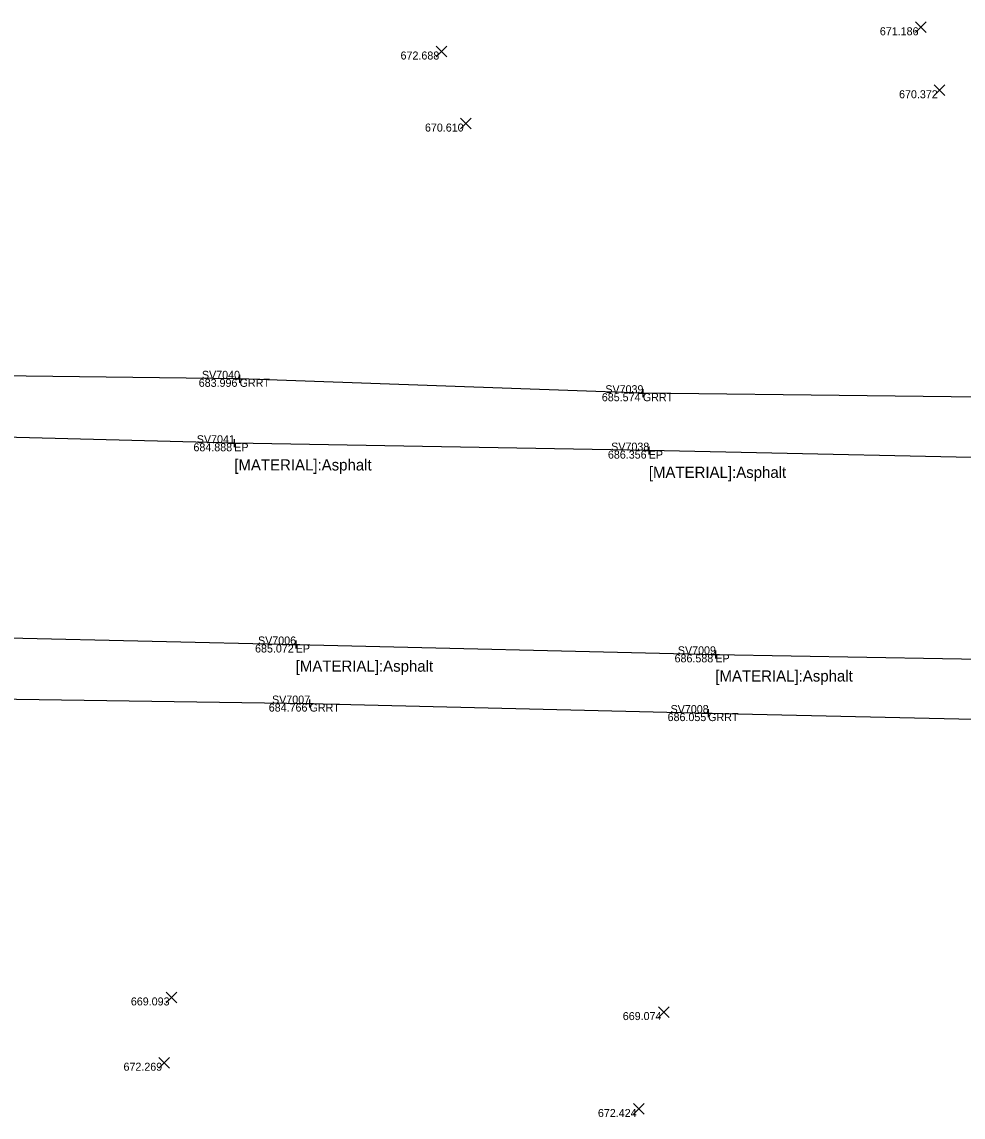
# Model space of a CAD drawing. Extents: x 1660019 to 1662995, y 619975 to 620342.
# Drawn here: x 1660723.1 to 1660840.7, y 620172.3 to 620309.1 of the extents above; entities that cross this region are included whole.
import ezdxf

# ---------------------------------------------------------------- set-up
doc = ezdxf.new("R2010")
doc.units = 0
for name, color, linetype in [('BR_X_Rail_Object', 7, 'Continuous'), ('PV_X_EOP', 7, 'Continuous'), ('RD_P_GR_Lt', 7, 'Continuous'), ('RD_P_GR_Rt', 7, 'Continuous'), ('RD_X_GR_Bar', 7, 'Continuous'), ('RD_X_GR_Rt', 7, 'Continuous'), ('RD_X_Wall', 7, 'Continuous'), ('SV_X_Text', 7, 'Continuous')]:
    doc.layers.add(name, color=color, linetype=linetype)

msp = doc.modelspace()

# ---------------------------------------------------------------- linework, layer by layer
at = {"layer": 'PV_X_EOP'}
for points in [[(1661208.92, 620246.9), (1661156.94, 620248.21), (1661087.29, 620250.6), (1661037.39, 620250.48), (1660981.01, 620252.16), (1660916.41, 620253.34), (1660855.2, 620254.44), (1660801.44, 620255.57), (1660749.64, 620256.49), (1660700.03, 620257.78), (1660643.44, 620258.64), (1660593.17, 620259.57)], [(1660597.37, 620234.1), (1660651.64, 620233.44), (1660703.42, 620232.61), (1660757.32, 620231.35), (1660809.76, 620230.12), (1660857.03, 620229.26), (1660910.07, 620228.44), (1660968.25, 620227.38), (1661028.27, 620226.15), (1661081.58, 620225.11), (1661140.41, 620223.53), (1661201.71, 620222.7)]]:
    msp.add_lwpolyline(points, dxfattribs=at)
at = {"layer": 'RD_P_GR_Lt'}
for p, q in [((1660749.81, 620264.54), (1660750.81, 620264.54)), ((1660750.31, 620265.04), (1660750.31, 620264.04)), ((1660750.31, 620264.54), (1660750.31, 620264.54)), ((1660800.7, 620263.24), (1660800.7, 620262.24)), ((1660800.2, 620262.74), (1660801.2, 620262.74)), ((1660800.7, 620262.74), (1660800.7, 620262.74)), ((1660749.14, 620256.49), (1660750.14, 620256.49)), ((1660749.64, 620256.99), (1660749.64, 620255.99)), ((1660749.64, 620256.49), (1660749.64, 620256.49)), ((1660800.94, 620255.57), (1660801.94, 620255.57)), ((1660801.44, 620256.07), (1660801.44, 620255.07)), ((1660801.44, 620255.57), (1660801.44, 620255.57)), ((1660757.32, 620231.85), (1660757.32, 620230.85)), ((1660756.82, 620231.35), (1660757.82, 620231.35)), ((1660757.32, 620231.35), (1660757.32, 620231.35)), ((1660809.26, 620230.12), (1660810.26, 620230.12)), ((1660809.76, 620230.62), (1660809.76, 620229.62)), ((1660809.76, 620230.12), (1660809.76, 620230.12)), ((1660758.55, 620223.97), (1660759.55, 620223.97)), ((1660759.05, 620224.47), (1660759.05, 620223.47)), ((1660759.05, 620223.97), (1660759.05, 620223.97)), ((1660808.86, 620223.28), (1660808.86, 620222.28)), ((1660808.36, 620222.78), (1660809.36, 620222.78)), ((1660808.86, 620222.78), (1660808.86, 620222.78))]:
    msp.add_line(p, q, dxfattribs=at)
at = {"layer": 'RD_P_GR_Rt'}
for p, q in [((1660834.75, 620307.79), (1660836.08, 620309.13)), ((1660834.75, 620309.13), (1660836.08, 620307.79)), ((1660774.86, 620304.76), (1660776.19, 620306.1)), ((1660774.86, 620306.1), (1660776.19, 620304.76)), ((1660837.11, 620299.92), (1660838.45, 620301.26)), ((1660837.11, 620301.26), (1660838.45, 620299.92)), ((1660777.92, 620295.76), (1660779.25, 620297.1)), ((1660777.92, 620297.1), (1660779.25, 620295.76)), ((1660741.12, 620186.59), (1660742.45, 620187.93)), ((1660741.12, 620187.93), (1660742.45, 620186.59)), ((1660802.64, 620184.76), (1660803.98, 620186.1)), ((1660802.64, 620186.1), (1660803.98, 620184.76)), ((1660740.22, 620178.43), (1660741.55, 620179.77)), ((1660740.22, 620179.77), (1660741.55, 620178.43)), ((1660799.54, 620172.66), (1660800.87, 620173.99)), ((1660799.54, 620173.99), (1660800.87, 620172.66))]:
    msp.add_line(p, q, dxfattribs=at)
at = {"layer": 'RD_X_GR_Rt'}
for points in [[(1661224.69, 620250.79), (1661156.18, 620253.35), (1661087.54, 620257.19), (1661037.26, 620258.5), (1660981.37, 620259.47), (1660918.68, 620260.81), (1660856.77, 620262.08), (1660800.7, 620262.74), (1660750.31, 620264.54), (1660700.27, 620265.16), (1660644.43, 620266.52), (1660592.86, 620267.53)], [(1660596.86, 620226.32), (1660650.68, 620225.81), (1660702.7, 620224.83), (1660759.05, 620223.97), (1660808.86, 620222.78), (1660856.77, 620221.69), (1660908.98, 620220.55), (1660971.26, 620219.59), (1661027.54, 620217.92), (1661083.51, 620217.29), (1661139.61, 620218.11), (1661215.13, 620218.24)]]:
    msp.add_lwpolyline(points, dxfattribs=at)

# ---------------------------------------------------------------- texts
at = {"layer": 'BR_X_Rail_Object'}
for s, p in [('GRRT', (1660750.31, 620263.54)), ('GRRT', (1660800.7, 620261.74)), ('EP', (1660749.64, 620255.49)), ('EP', (1660801.44, 620254.57)), ('EP', (1660757.32, 620230.35)), ('EP', (1660809.76, 620229.12)), ('GRRT', (1660759.05, 620222.97)), ('GRRT', (1660808.86, 620221.78))]:
    msp.add_text(s, height=1, dxfattribs=at).set_placement(p)
at = {"layer": 'RD_X_GR_Bar'}
for s, p in [('671.186', (1660830.31, 620307.46)), ('672.688', (1660770.42, 620304.43)), ('670.372', (1660832.71, 620299.59)), ('670.610', (1660773.47, 620295.43)), ('683.996', (1660745.2, 620263.54)), ('685.574', (1660795.57, 620261.74)), ('684.888', (1660744.54, 620255.49)), ('686.356', (1660796.33, 620254.57)), ('685.072', (1660752.24, 620230.35)), ('686.588', (1660804.66, 620229.12)), ('684.766', (1660753.95, 620222.97)), ('686.055', (1660803.79, 620221.78)), ('669.093', (1660736.72, 620186.26)), ('669.074', (1660798.19, 620184.43)), ('672.269', (1660735.8, 620178.1)), ('672.424', (1660795.08, 620172.32))]:
    msp.add_text(s, height=1, dxfattribs=at).set_placement(p)
at = {"layer": 'RD_X_Wall'}
for s, p in [('SV7040', (1660745.6, 620264.54)), ('SV7039', (1660796.01, 620262.74)), ('SV7041', (1660744.96, 620256.49)), ('SV7038', (1660796.74, 620255.57)), ('SV7006', (1660752.61, 620231.35)), ('SV7009', (1660805.07, 620230.12)), ('SV7007', (1660754.36, 620223.97)), ('SV7008', (1660804.16, 620222.78))]:
    msp.add_text(s, height=1, dxfattribs=at).set_placement(p)
at = {"layer": 'SV_X_Text'}
for p in [(1660749.64, 620253.09), (1660801.44, 620252.17), (1660757.32, 620227.95), (1660809.76, 620226.72)]:
    msp.add_text('[MATERIAL]:Asphalt', height=1.4, dxfattribs=at).set_placement(p)

doc.saveas('drawing.dxf')
